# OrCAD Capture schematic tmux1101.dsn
size A
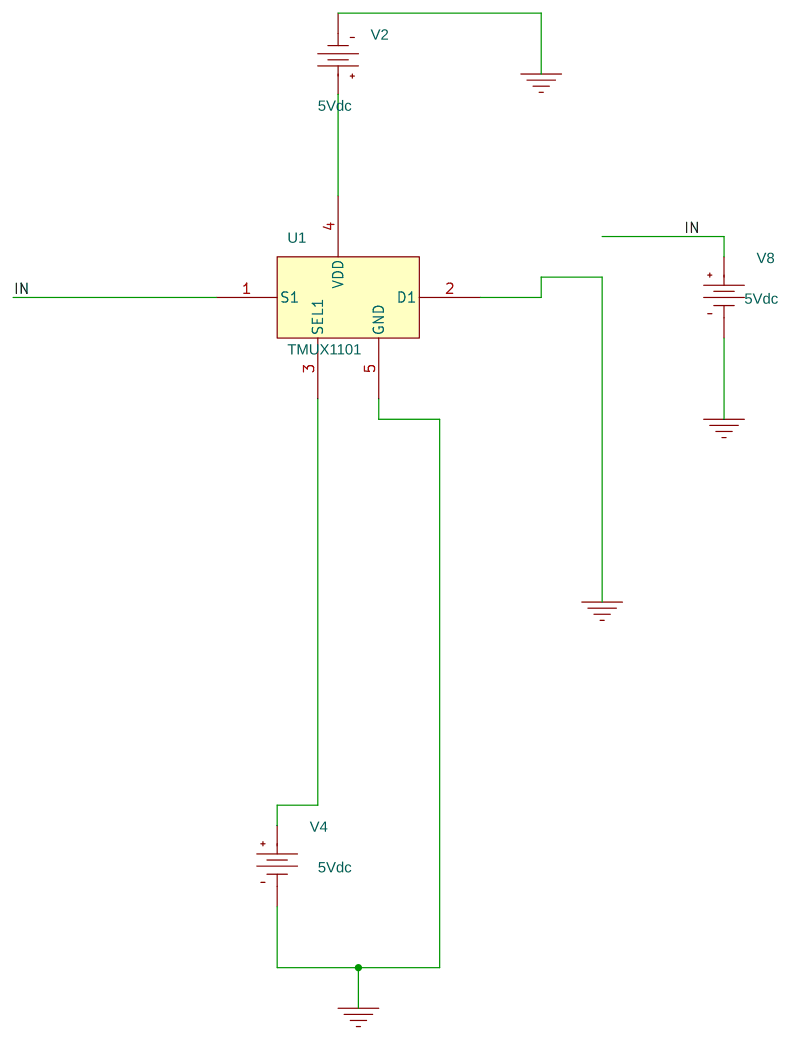
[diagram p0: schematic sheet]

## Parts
U1  TMUX1101
V2  VDC
V4  VDC
V8  VDC

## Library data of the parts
U1 = TMUX1101
V2 V4 V8 = VDC: DC: 5Vdc

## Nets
0: U1.2(D1) U1.5(GND) V2.1(-) V4.1(-) V8.1(-)
IN: U1.1(S1) V8.0(+)
N03147: U1.4(VDD) V2.0(+)
N03237: U1.3(SEL1) V4.0(+)
